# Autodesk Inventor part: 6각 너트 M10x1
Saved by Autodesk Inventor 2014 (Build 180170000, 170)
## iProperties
Created: 2026-06
Part Number: 6각 너트 M10x1
Material: 강철, 연강
Document SubType Name: Modeling
Designer: dg
Density: 7.86 g/cm^3
Appearance: 강철
Mass: 11.7322 g
Surface Area: 10.7181 cm^2
Volume: 1.49264 cm^3
Author: jhkim
Description: 6각 너트 및 6각 가는 너트
Creation Date: 2026-05-29
Sending System: Autodesk Inventor 2027
Preprocessor: ST-DEVELOPER v20.1
Author: dg
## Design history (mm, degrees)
node "6각 너트 M10x11"
body "Solid1"
node "기준1"
